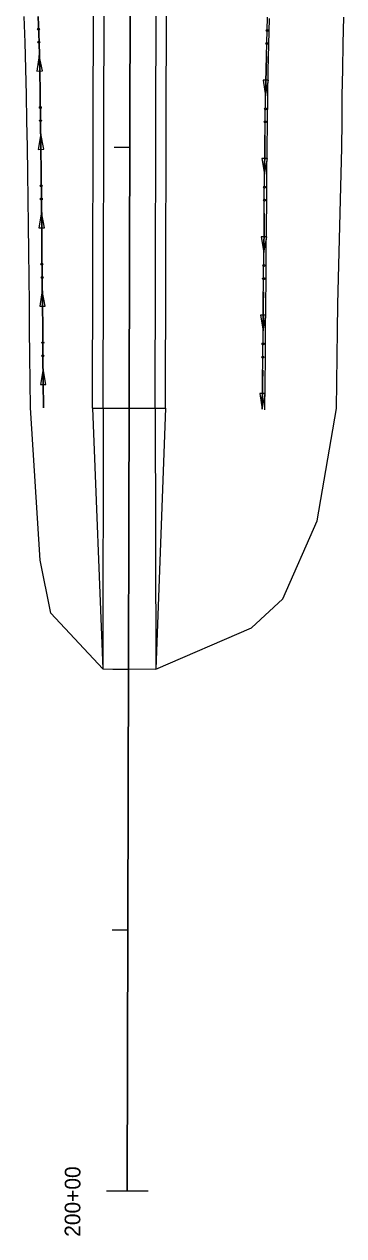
# Model space of a CAD drawing. Extents: x 1611108 to 1749517, y 619561 to 797725.
# Drawn here: x 1717571.3 to 1717693.9, y 765220.8 to 765685.2 of the extents above; entities that cross this region are included whole.
import ezdxf

# ---------------------------------------------------------------- set-up
doc = ezdxf.new("R2010")
doc.units = 0
for name, color, linetype in [('Level 8', 7, 'Continuous'), ('R_Ditch', 7, 'Continuous'), ('R_Horz Alg', 7, 'Continuous'), ('R_Horz Alg Stationing_Side Road', 7, 'Continuous'), ('R_Proposed Const Limits', 7, 'Continuous'), ('R_Proposed Road', 7, 'Continuous'), ('R_Special Ditch', 7, 'Continuous')]:
    doc.layers.add(name, color=color, linetype=linetype)

msp = doc.modelspace()

# ---------------------------------------------------------------- linework, layer by layer
at = {"layer": 'Level 8'}
msp.add_line((1717616.46, 767638.01), (1717610.87, 765238.01), dxfattribs=at)
at = {"layer": 'R_Ditch'}
for p, q in [((1717665.06, 765663.7), (1717662.94, 765663.75)), ((1717662.94, 765663.75), (1717663.88, 765657.73)), ((1717663.88, 765657.73), (1717665.06, 765663.7)), ((1717664.62, 765633.68), (1717662.51, 765633.7)), ((1717662.51, 765633.7), (1717663.51, 765627.69)), ((1717663.51, 765627.69), (1717664.62, 765633.68)), ((1717664.33, 765603.64), (1717662.22, 765603.66)), ((1717662.22, 765603.66), (1717663.22, 765597.65)), ((1717663.22, 765597.65), (1717664.33, 765603.64)), ((1717664.05, 765573.61), (1717661.93, 765573.63)), ((1717661.93, 765573.63), (1717662.93, 765567.62)), ((1717662.93, 765567.62), (1717664.05, 765573.61)), ((1717663.76, 765543.57), (1717661.65, 765543.59)), ((1717661.65, 765543.59), (1717662.65, 765537.58)), ((1717662.65, 765537.58), (1717663.76, 765543.57))]:
    msp.add_line(p, q, dxfattribs=at)
for points in [[(1717578.7, 765538.09), (1717578.6, 765548.09), (1717578.51, 765558.09), (1717578.41, 765568.09), (1717578.31, 765578.09), (1717578.22, 765588.09), (1717578.12, 765598.09), (1717578.02, 765608.09), (1717577.93, 765618.09), (1717577.83, 765628.09), (1717577.73, 765638.09), (1717577.61, 765648.09), (1717577.45, 765658.09), (1717577.25, 765668.09), (1717577, 765678.09), (1717576.71, 765688.09)], [(1717578.7, 765538.09), (1717578.6, 765548.09), (1717578.51, 765558.09), (1717578.41, 765568.09), (1717578.31, 765578.09), (1717578.22, 765588.09), (1717578.12, 765598.09), (1717578.02, 765608.09), (1717577.93, 765618.09), (1717577.83, 765628.09), (1717577.73, 765638.09), (1717577.61, 765648.09), (1717577.45, 765658.09), (1717577.25, 765668.09), (1717577, 765678.09), (1717576.71, 765688.09)], [(1717578.7, 765538.09), (1717578.6, 765548.09), (1717578.51, 765558.09), (1717578.41, 765568.09), (1717578.31, 765578.09), (1717578.22, 765588.09), (1717578.12, 765598.09), (1717578.02, 765608.09), (1717577.93, 765618.09), (1717577.83, 765628.09), (1717577.73, 765638.09), (1717577.61, 765648.09), (1717577.45, 765658.09), (1717577.25, 765668.09), (1717577, 765678.09), (1717576.71, 765688.09)], [(1717662.65, 765537.89), (1717662.74, 765547.89), (1717662.84, 765557.89), (1717662.94, 765567.89), (1717663.03, 765577.89), (1717663.13, 765587.89), (1717663.22, 765597.89), (1717663.32, 765607.89), (1717663.41, 765617.89), (1717663.51, 765627.89), (1717663.6, 765637.89), (1717663.72, 765647.89), (1717663.88, 765657.89), (1717664.08, 765667.89), (1717664.33, 765677.89), (1717664.62, 765687.89)], [(1717663.67, 765537.42), (1717663.76, 765547.42), (1717663.84, 765557.42), (1717663.92, 765567.42), (1717664.01, 765577.42), (1717664.09, 765587.42), (1717664.17, 765597.42), (1717664.26, 765607.42), (1717664.34, 765617.42), (1717664.42, 765627.42), (1717664.51, 765637.42), (1717664.61, 765647.41), (1717664.76, 765657.41), (1717664.95, 765667.41), (1717665.18, 765677.41), (1717665.46, 765687.41)], [(1717664.2, 765672.72), (1717664.08, 765667.89), (1717663.88, 765657.89), (1717663.88, 765657.73)], [(1717664.2, 765672.76), (1717664.2, 765672.72)], [(1717663.66, 765642.69), (1717663.6, 765637.89), (1717663.51, 765627.89), (1717663.51, 765627.69)], [(1717663.66, 765642.73), (1717663.66, 765642.69)], [(1717663.36, 765612.65), (1717663.32, 765607.89), (1717663.22, 765597.89), (1717663.22, 765597.65)], [(1717663.36, 765612.69), (1717663.36, 765612.65)], [(1717663.08, 765582.62), (1717663.03, 765577.89), (1717662.94, 765567.89), (1717662.93, 765567.62)], [(1717663.08, 765582.65), (1717663.08, 765582.62)], [(1717662.79, 765552.58), (1717662.74, 765547.89), (1717662.65, 765537.89)], [(1717662.79, 765552.62), (1717662.79, 765552.58)]]:
    msp.add_lwpolyline(points, dxfattribs=at)
for centre in [(1717664.5, 765682.75), (1717664.36, 765677.74), (1717663.83, 765652.72), (1717663.75, 765647.71), (1717663.49, 765622.68), (1717663.45, 765617.67), (1717663.21, 765592.65), (1717663.16, 765587.64), (1717662.92, 765562.61), (1717662.87, 765557.6)]:
    msp.add_circle(centre, 0.375, dxfattribs=at)
at = {"layer": 'R_Horz Alg'}
msp.add_line((1717610.87, 765238.01), (1717616.46, 767638.01), dxfattribs=at)
at = {"layer": 'R_Horz Alg Stationing_Side Road'}
for points in [[(1717605.8, 765638.03), (1717611.8, 765638.01)], [(1717605.57, 765538.03), (1717611.57, 765538.01)], [(1717605.34, 765438.03), (1717611.34, 765438.01)], [(1717605.1, 765338.03), (1717611.1, 765338.01)], [(1717602.87, 765238.03), (1717618.87, 765237.99)]]:
    msp.add_lwpolyline(points, dxfattribs=at)
at = {"layer": 'R_Proposed Const Limits'}
for points in [[(1717601.42, 765438.04), (1717581.48, 765459.47), (1717577.44, 765479.79), (1717573.72, 765538.1), (1717573.61, 765548.1), (1717573.52, 765558.1), (1717573.41, 765568.1), (1717573.3, 765578.1), (1717573.19, 765588.1), (1717573.09, 765598.1), (1717572.98, 765608.1), (1717572.86, 765618.1), (1717572.71, 765628.1), (1717572.56, 765638.1), (1717572.38, 765648.1), (1717572.17, 765658.1), (1717571.91, 765668.11), (1717571.63, 765678.11), (1717571.32, 765688.11)], [(1717621.8, 765437.99), (1717658.49, 765453.86), (1717670.54, 765464.92), (1717683.71, 765494.81), (1717691.11, 765537.83), (1717691.23, 765547.83), (1717691.36, 765557.83), (1717691.5, 765567.83), (1717691.64, 765577.83), (1717691.82, 765587.83), (1717692.1, 765597.83), (1717692.39, 765607.82), (1717692.65, 765617.82), (1717692.91, 765627.82), (1717693.16, 765637.82), (1717693.23, 765647.82), (1717693.34, 765657.82), (1717693.49, 765667.82), (1717693.67, 765677.82), (1717693.9, 765687.82)]]:
    msp.add_lwpolyline(points, dxfattribs=at)
at = {"layer": 'R_Proposed Road'}
for p, q in [((1717597.57, 765538.05), (1717601.76, 767338.04)), ((1717601.57, 765538.04), (1717605.76, 767338.03)), ((1717621.57, 765537.99), (1717625.76, 767337.98)), ((1717625.57, 765537.98), (1717629.76, 767337.98)), ((1717597.57, 765538.05), (1717625.57, 765537.98)), ((1717597.57, 765538.05), (1717601.42, 765438.04)), ((1717601.57, 765538.04), (1717601.42, 765438.04)), ((1717621.57, 765537.99), (1717621.8, 765437.99)), ((1717625.57, 765537.98), (1717621.8, 765437.99)), ((1717601.42, 765438.04), (1717621.8, 765437.99))]:
    msp.add_line(p, q, dxfattribs=at)
at = {"layer": 'R_Special Ditch'}
for p, q in [((1717577.12, 765673.23), (1717576.21, 765667.21)), ((1717578.33, 765667.26), (1717577.12, 765673.23)), ((1717576.21, 765667.21), (1717578.33, 765667.26)), ((1717577.67, 765643.2), (1717576.68, 765637.19)), ((1717578.8, 765637.21), (1717577.67, 765643.2)), ((1717576.68, 765637.19), (1717578.8, 765637.21)), ((1717577.97, 765613.16), (1717576.97, 765607.15)), ((1717579.09, 765607.17), (1717577.97, 765613.16)), ((1717576.97, 765607.15), (1717579.09, 765607.17)), ((1717578.26, 765583.13), (1717577.26, 765577.12)), ((1717579.38, 765577.14), (1717578.26, 765583.13)), ((1717577.26, 765577.12), (1717579.38, 765577.14)), ((1717578.55, 765553.09), (1717577.55, 765547.08)), ((1717579.67, 765547.1), (1717578.55, 765553.09)), ((1717577.55, 765547.08), (1717579.67, 765547.1))]:
    msp.add_line(p, q, dxfattribs=at)
for points in [[(1717576.71, 765688.09), (1717577, 765678.09), (1717577.25, 765668.09), (1717577.45, 765658.09), (1717577.61, 765648.09), (1717577.73, 765638.09), (1717577.83, 765628.09), (1717577.93, 765618.09), (1717578.02, 765608.09), (1717578.12, 765598.09), (1717578.22, 765588.09), (1717578.31, 765578.09), (1717578.41, 765568.09), (1717578.51, 765558.09), (1717578.6, 765548.09), (1717578.7, 765538.09)], [(1717577.45, 765658.23), (1717577.25, 765668.09), (1717577.12, 765673.23)], [(1717577.45, 765658.2), (1717577.45, 765658.23)], [(1717577.83, 765628.2), (1717577.73, 765638.09), (1717577.67, 765643.2)], [(1717577.83, 765628.16), (1717577.83, 765628.2)], [(1717578.12, 765598.16), (1717578.02, 765608.09), (1717577.97, 765613.16)], [(1717578.12, 765598.12), (1717578.12, 765598.16)], [(1717578.41, 765568.13), (1717578.31, 765578.09), (1717578.26, 765583.13)], [(1717578.41, 765568.09), (1717578.41, 765568.09), (1717578.41, 765568.13)], [(1717578.7, 765538.09), (1717578.6, 765548.09), (1717578.55, 765553.09)]]:
    msp.add_lwpolyline(points, dxfattribs=at)
for centre in [(1717576.82, 765683.24), (1717576.96, 765678.23), (1717577.5, 765653.21), (1717577.58, 765648.2), (1717577.84, 765623.18), (1717577.89, 765618.17), (1717578.13, 765593.14), (1717578.18, 765588.13), (1717578.42, 765563.1), (1717578.47, 765558.09)]:
    msp.add_circle(centre, 0.375, dxfattribs=at)

# ---------------------------------------------------------------- texts
at = {"layer": 'R_Horz Alg Stationing_Side Road'}
msp.add_text('200+00', height=6, rotation=89.8667, dxfattribs=at).set_placement((1717592.83, 765220.41))

doc.saveas('drawing.dxf')
